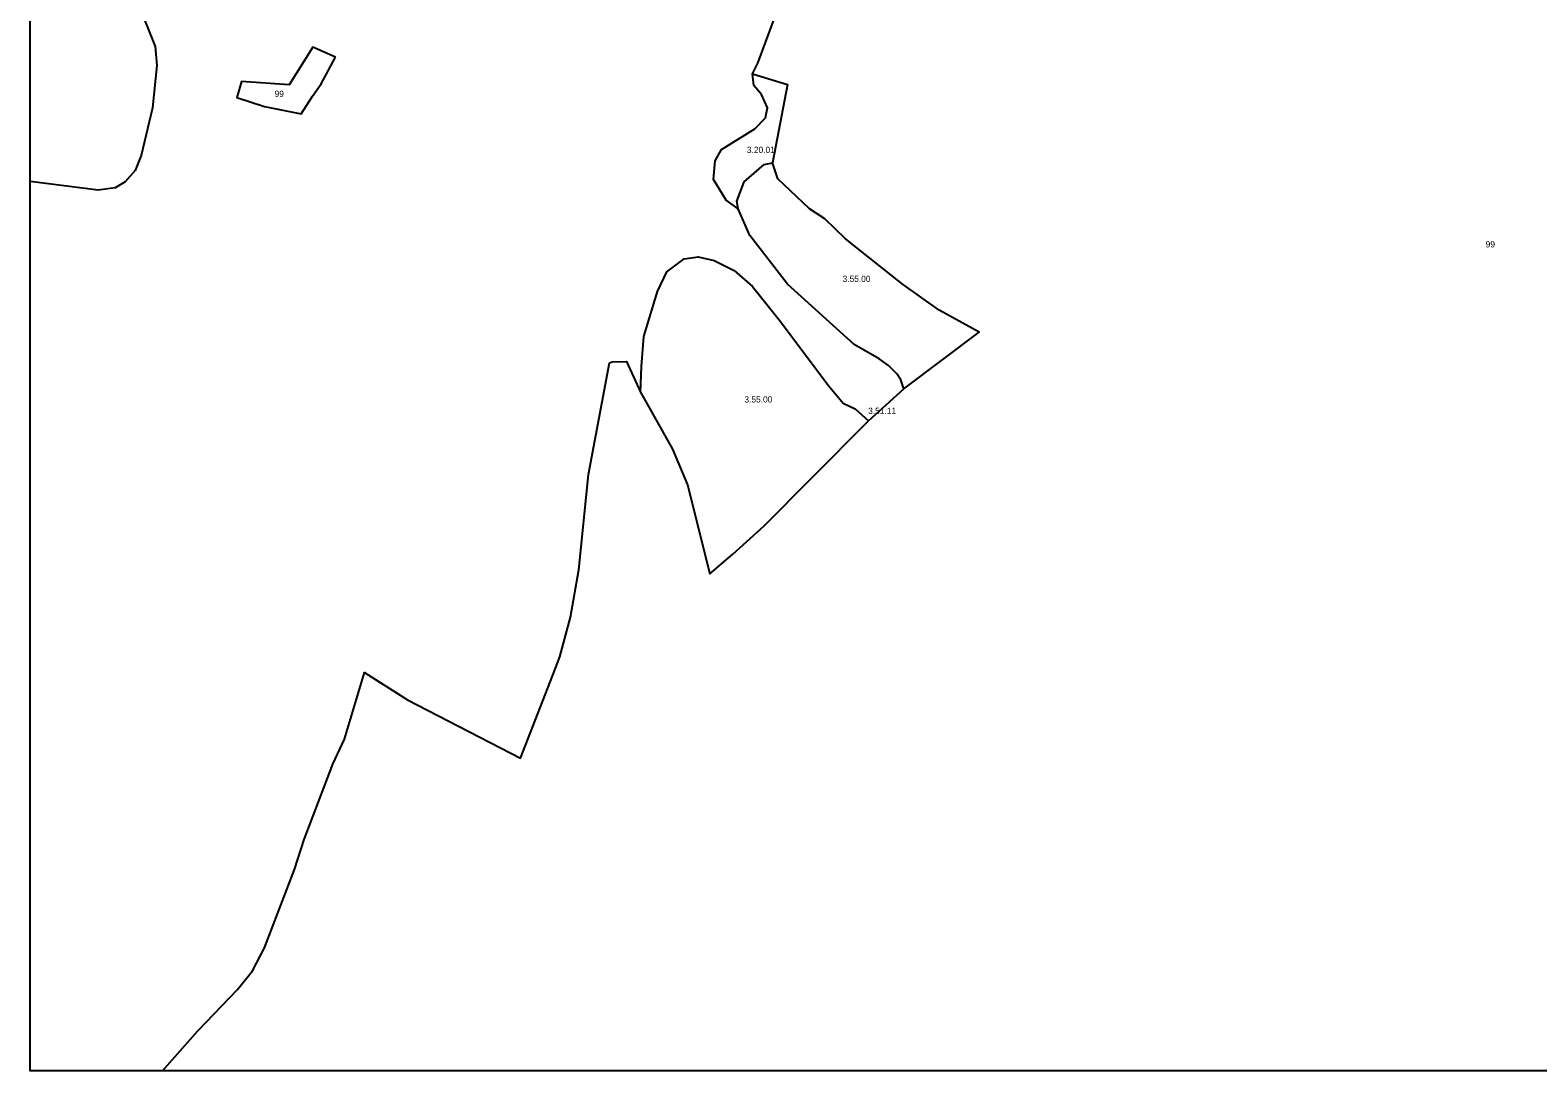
# Model space of a CAD drawing. Extents: x -662500 to -653478, y -1056827 to -1049993.
# Drawn here: x -662500 to -660692, y -1056000 to -1054752 of the extents above; entities that cross this region are included whole.
import ezdxf

# ---------------------------------------------------------------- set-up
doc = ezdxf.new("R2010")
doc.units = 0
doc.layers.add('Vrstva 24', color=7, linetype='Continuous')

msp = doc.modelspace()

# ---------------------------------------------------------------- linework, layer by layer
at = {"layer": 'Vrstva 24'}
for points in [[(-662222, -1054642.5), (-662258, -1054638), (-662306, -1054620), (-662332, -1054614.5), (-662345.5, -1054614), (-662362, -1054618), (-662379, -1054632.5), (-662385.5, -1054646), (-662386, -1054668.5), (-662377, -1054704.5), (-662350, -1054772), (-662348, -1054794.5), (-662353.5, -1054845.5), (-662367, -1054902.5), (-662374, -1054920.5), (-662386, -1054934), (-662398, -1054941.5), (-662418.5, -1054944), (-662500, -1054933.6)], [(-662500, -1054933.6), (-662500, -1054639.9)], [(-661634, -1054804.5), (-661627.5, -1054792), (-661600, -1054717.5), (-661604, -1054717.5), (-661685.5, -1054715), (-661795.5, -1054702.5), (-661984, -1054662.5), (-662080, -1054645.5), (-662111, -1054702), (-662174, -1054671.5), (-662222, -1054642.5)], [(-661651, -1054966.5), (-661665.5, -1054956), (-661680.5, -1054931.5), (-661678.5, -1054909), (-661671, -1054895.5), (-661631, -1054870.5), (-661618.5, -1054857.5), (-661616, -1054845.5), (-661623, -1054829.5), (-661632.5, -1054818.5), (-661634, -1054804.5)], [(-661634, -1054804.5), (-661592, -1054817.5), (-661610, -1054911.5)], [(-660000, -1054894.3), (-660000, -1056000), (-662341.2, -1056000)], [(-661651, -1054966.5), (-661652.5, -1054957.5), (-661644, -1054934), (-661620, -1054913.5), (-661610, -1054911.5)], [(-661452.5, -1055182.5), (-661362, -1055114.5), (-661410, -1055088), (-661454.5, -1055056.5), (-661522.5, -1055002.5), (-661547, -1054978.5), (-661565.5, -1054966.5), (-661603.5, -1054930.5), (-661610, -1054911.5)], [(-662341.2, -1056000), (-662500, -1056000), (-662500, -1054933.6)], [(-661452.5, -1055182.5), (-661456, -1055171.5), (-661461, -1055164.5), (-661471, -1055154.5), (-661482, -1055146.5), (-661512, -1055129), (-661592, -1055057), (-661637, -1054998.5), (-661651, -1054966.5)], [(-661768, -1055186.5), (-661767, -1055155.5), (-661764, -1055119.5), (-661748, -1055065.5), (-661736.5, -1055042), (-661716, -1055026.5), (-661699, -1055024), (-661680, -1055028.5), (-661656, -1055040.5), (-661634, -1055059.5), (-661600.5, -1055101.5), (-661543, -1055178), (-661525, -1055199.5), (-661511, -1055206.5), (-661495, -1055220.5)], [(-662341.2, -1056000), (-662299, -1055952), (-662251.5, -1055902.5), (-662233.5, -1055880), (-662219, -1055852.5), (-662201.5, -1055806.5), (-662183, -1055758.5), (-662171.5, -1055722.5), (-662137, -1055632.5), (-662123, -1055602.5), (-662099, -1055522.5), (-662047.5, -1055555), (-661912, -1055625), (-661873.5, -1055525.5), (-661865, -1055503.5), (-661852, -1055456), (-661842, -1055399.5), (-661830.5, -1055285), (-661805.5, -1055151), (-661802, -1055150), (-661785, -1055149.5), (-661768, -1055186.5)], [(-661495, -1055220.5), (-661452.5, -1055182.5)], [(-661768, -1055186.5), (-661730, -1055254.5), (-661712, -1055297.5), (-661685, -1055404), (-661657.5, -1055380.5), (-661620, -1055346.5), (-661563, -1055289.5), (-661495, -1055220.5)]]:
    msp.add_lwpolyline(points, dxfattribs=at)
msp.add_lwpolyline([(-662134, -1054784.5), (-662161, -1054772.5), (-662189.5, -1054818), (-662246.5, -1054814), (-662252, -1054833), (-662219, -1054844), (-662175, -1054852.5), (-662161.5, -1054831.5), (-662151, -1054816.5)], close=True, dxfattribs=at)

# ---------------------------------------------------------------- texts
for s, p in [('99', (-662206.9, -1054832.3)), ('3.20.01', (-661640.6, -1054899.6)), ('99', (-660754.8, -1055012.8)), ('3.55.00', (-661525.9, -1055054.2)), ('3.55.00', (-661643.6, -1055198.7)), ('3.51.11', (-661495.2, -1055212.5))]:
    msp.add_text(s, height=7.5, dxfattribs=at).set_placement(p)

doc.saveas('drawing.dxf')
